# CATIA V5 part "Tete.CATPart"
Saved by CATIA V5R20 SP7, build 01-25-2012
Part number: Tete
Bounding box of the stored display mesh (mm): x -43.469 to 43.469, y -43.436 to 43.436, z -280 to -6
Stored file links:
  F:\Travaux\Modélisations\CFAO_2011\MMS\MMS_GR1\AA_OK\bmadec\Catia\Tete.CATPart
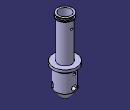
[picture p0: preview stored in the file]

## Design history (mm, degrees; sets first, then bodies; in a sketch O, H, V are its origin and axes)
Body1 (main body)
  Sketch1 on yz-plane, origin (0, 0, 0), H (0, 1, 0), V (0, 0, 1)
    line L1 (28, -6) -> (28, -19.5)
    line L2 (28, -19.5) -> (24.75, -19.5)
    line L3 (24.75, -19.5) -> (24.75, -160)
    line L4 (24.75, -160) -> (43.5, -160)
    line L5 (43.5, -160) -> (43.5, -170)
    line L6 (43.5, -170) -> (34.5, -178)
    line L7 (34.5, -178) -> (34.5, -244)
    line L8 (34.5, -244) -> (12, -274)
    point P9 (12, -274)
    arc A1 centre (0, -265) radius 15 from (12, -274) to (0, -280) cw
    point P10 (0, -265)
    point P11 (0, -280)
    line L9 (0, -280) -> (0, -178)
    line L10 (0, -178) -> (21, -178)
    line L11 (21, -178) -> (21, -6)
    line L12 (21, -6) -> (28, -6)
    distance L5 L9 = 43.5
    length L5 = 10
    distance L4 P11 = 120
    length L7 = 66
    distance P9 P11 V = 6
    distance L9 L7 = 34.5
    length L8 V = 30
    length L9 = 102
    length L1 = 13.5
    distance L1 V = 28
    distance L11 V = 21
    distance L12 H = 6
    distance L12 L4 = 154
    distance L3 V = 24.75
    vertical: L1 V, L3 V, L5 V, L7 V, L9 V, L11 V
    horizontal: L2 H, L4 H, L10 H, L12 H
    coincidence: P11 V, P10 L9
    tangency: A1 L8
  Shaft1: profile Sketch1, axis Sketch1.V, angle 360
  Sketch2 on yz-plane, origin (0, 0, 0), H (0, 1, 0), V (0, 0, 1)
    line L1 (30.4275, -9) -> (24, -9)
    line L2 (24, -9) -> (24, -16.5)
    line L3 (24, -16.5) -> (30.4275, -16.5)
    line L4 (30.4275, -16.5) -> (30.4275, -9)
    reference projected line E1 through (0, 0) direction (0, 1) from axis of face of Shaft1 from Sketch1.L1
    reference projected line E2 (-28, -6) -> (28, -6) from edge [face of Shaft1 from Sketch1.L1 | face of Shaft1 from Sketch1.L12]
    distance L2 E1 = 24
    distance E2 L1 = 3
    length L2 = 7.5
    horizontal: L1 H, L3 H
    vertical: L2 V, L4 V
  Groove1: profile Sketch2, axis Sketch2.V, angle 360
  Sketch3 on face of Shaft1 from Sketch1.L10, origin (0, 0, -178), H (1, 0, 0), V (0, 1, 0)
    point P1 (0, 0)
    coincidence: P1 O
  Hole1: placed by Sketch3, at (0, 0, -178) direction (0, 0, -1), diameter 19.5, depth 84, V-bottom angle 120
  Sketch4 on {plane type Tangent, Support face of Shaft1 from Sketch1.L3, RefPoint {point type OnSurface, Support face of Shaft1 from Sketch1.L3, RefPoint {point stored without definition}, Length 0, Direction (0, 0, 1000)}}, origin (2.29, -24.6438, -50.3284), H (0.9957, 0.0925, 0), V (0, 0, -1)
    point P1 (-2.2998, -2.8284)
    reference intersected line E1 through (-2.2998, 0) direction (0, 1) from yz-plane
    reference projected line E2 (28, -44.3284) -> (-28, -44.3284) from edge [face of Shaft1 from Sketch1.L1 | face of Shaft1 from Sketch1.L12]
    distance P1 E2 = 41.5
    coincidence: P1 E1
  Hole2: placed by Sketch4, at (0, -24.75, -47.5) direction (0, 1, 0), diameter 7.5, up to face of Shaft1 from Sketch1.L3
  Sketch5 on {plane type Tangent, Support face of Shaft1 from Sketch1.L7, RefPoint {point type OnSurface, Support face of Shaft1 from Sketch1.L7, RefPoint {point stored without definition}, Length 0, Direction (0, 0, -1000)}}, origin (-2.7956, 34.3865, -187.7113), H (0.9967, 0.081, 0), V (0, 0, 1)
    point P1 (2.8048, 0.7113)
    reference intersected line E1 through (2.8048, 0) direction (0, 1) from yz-plane
    reference projected line E2 (-43.5, 27.7113) -> (43.5, 27.7113) from edge [face of Shaft1 from Sketch1.L5 | face of Shaft1 from Sketch1.L4]
    distance P1 E2 = 27
    coincidence: P1 E1
  Hole3: placed by Sketch5, at (0, 34.5, -187) direction (0, -1, 0), diameter 9.75, through (limit type 6)
  Sketch6 on {plane type Tangent, Support face of Shaft1 from Sketch1.L7, RefPoint {point type OnSurface, Support face of Shaft1 from Sketch1.L7, RefPoint {point stored without definition}, Length 0, Direction (0, 0, 1000)}}, origin (1.6006, -34.4628, -186.8843), H (0.9989, 0.0464, 0), V (0, 0, -1)
    point P1 (-1.6024, 0.1157)
    reference intersected line E1 through (-1.6024, 0) direction (0, 1) from yz-plane
    reference projected line E2 (43.5, -26.8843) -> (-43.5, -26.8843) from edge [face of Shaft1 from Sketch1.L5 | face of Shaft1 from Sketch1.L4]
    distance P1 E2 = 27
    coincidence: P1 E1
  Hole4: placed by Sketch6, at (0, -34.5, -187) direction (0, 1, 0), diameter 15, through (limit type 6)
  Sketch7 on {plane type Tangent, Support face of Shaft1 from Sketch1.L7, RefPoint {point type OnSurface, Support face of Shaft1 from Sketch1.L7, RefPoint {point stored without definition}, Length 0, Direction (0, 0, -1000)}}, origin (-2.2408, 34.4272, -212.5338), H (0.9979, 0.0649, 0), V (0, 0, 1)
    point P1 (2.2455, -17.9662)
    reference intersected line E1 through (2.2455, 0) direction (0, 1) from yz-plane
    reference projected line E2 (-43.5, 52.5338) -> (43.5, 52.5338) from edge [face of Shaft1 from Sketch1.L5 | face of Shaft1 from Sketch1.L4]
    distance P1 E2 = 70.5
    coincidence: P1 E1
  Hole5: placed by Sketch7, at (0, 34.5, -230.5) direction (0, -1, 0), diameter 18, through (limit type 6)
  CircPattern1: of Hole5, instances 3, angular step 120, axis from face of Shaft1 from Sketch1.L7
